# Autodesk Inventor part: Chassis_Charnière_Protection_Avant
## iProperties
Created: 2009-01
Part Number: Chassis_Charnière_Protection_Avant
Document SubType Name: Modeling
Designer: claivier
Author: claivier
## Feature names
1. Extrusion1
2. Extrusion2
3. Réseau rectangulaire1 [Rectangular Pattern]
4. Perçage1 [Hole]
